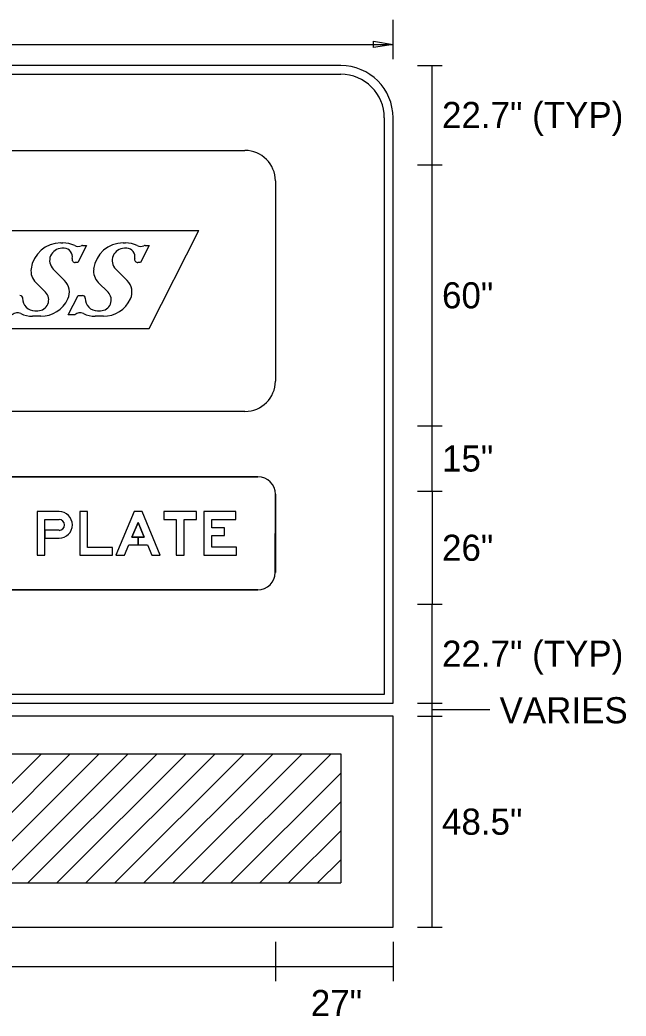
# Model space of a CAD drawing. Extents: x 10268312 to 10268706, y 2142548 to 2142786.
# Drawn here: x 10268686.56 to 10268703.79, y 2142607.94 to 2142636.28 of the extents above; entities that cross this region are included whole.
import ezdxf

# ---------------------------------------------------------------- set-up
doc = ezdxf.new("R2010")
doc.units = 0
for name, color, linetype in [('GSBWFill', 7, 'Continuous'), ('GSDims', 7, 'Continuous'), ('SignPanel', 7, 'Continuous'), ('TextMisc', 7, 'Continuous')]:
    doc.layers.add(name, color=color, linetype=linetype)

msp = doc.modelspace()

# ---------------------------------------------------------------- linework, layer by layer
at = {"layer": 'GSBWFill'}
for p, q in [((10268697.169, 2142635.162), (10268697.169, 2142636.276)), ((10268695.683, 2142634.977), (10268671.916, 2142634.977)), ((10268671.916, 2142634.73), (10268695.683, 2142634.73)), ((10268696.921, 2142633.492), (10268696.921, 2142617.09)), ((10268674.27, 2142623.279), (10268693.329, 2142623.279)), ((10268674.27, 2142623.279), (10268693.329, 2142623.279)), ((10268693.824, 2142622.784), (10268693.824, 2142620.556)), ((10268693.824, 2142622.784), (10268693.824, 2142620.556)), ((10268693.329, 2142620.061), (10268674.27, 2142620.061)), ((10268693.329, 2142620.061), (10268674.27, 2142620.061))]:
    msp.add_line(p, q, dxfattribs=at)
msp.add_lwpolyline([(10268696.921, 2142617.09), (10268670.686, 2142617.09), (10268670.686, 2142616.842), (10268697.169, 2142616.842), (10268697.169, 2142616.842), (10268697.169, 2142633.492)], dxfattribs=at)
for centre, radius, start, end in [((10268695.683, 2142633.492), 1.485, 0, 90), ((10268695.683, 2142633.492), 1.238, 0, 90), ((10268693.329, 2142622.784), 0.495, 0, 90), ((10268693.329, 2142622.784), 0.495, 0, 90), ((10268693.324, 2142620.556), 0.495, 270, 0), ((10268693.324, 2142620.556), 0.495, 270, 0)]:
    msp.add_arc(centre, radius, start, end, dxfattribs=at)
at = {"layer": 'GSDims'}
for p, q in [((10268670.431, 2142635.58), (10268697.169, 2142635.58)), ((10268697.865, 2142634.977), (10268698.561, 2142634.977)), ((10268698.283, 2142632.167), (10268698.283, 2142634.977)), ((10268698.561, 2142634.977), (10268698.561, 2142634.977)), ((10268697.865, 2142632.155), (10268698.561, 2142632.155)), ((10268698.283, 2142624.729), (10268698.283, 2142632.167)), ((10268697.865, 2142624.729), (10268698.561, 2142624.729)), ((10268698.283, 2142622.871), (10268698.283, 2142624.729)), ((10268697.865, 2142622.871), (10268698.561, 2142622.871)), ((10268698.283, 2142622.871), (10268698.283, 2142619.652)), ((10268697.865, 2142619.652), (10268698.561, 2142619.652)), ((10268698.283, 2142616.842), (10268698.283, 2142619.652)), ((10268697.865, 2142616.842), (10268698.561, 2142616.842)), ((10268698.283, 2142616.471), (10268698.283, 2142616.842)), ((10268697.865, 2142616.471), (10268698.561, 2142616.471)), ((10268698.283, 2142616.657), (10268699.925, 2142616.657)), ((10268698.283, 2142610.467), (10268698.283, 2142616.471)), ((10268697.865, 2142610.467), (10268698.561, 2142610.467)), ((10268693.826, 2142610.05), (10268693.826, 2142608.936)), ((10268697.169, 2142610.05), (10268697.169, 2142608.936)), ((10268673.773, 2142609.353), (10268693.826, 2142609.353)), ((10268693.826, 2142609.353), (10268697.169, 2142609.353))]:
    msp.add_line(p, q, dxfattribs=at)
msp.add_lwpolyline([(10268697.169, 2142635.58), (10268696.611, 2142635.487), (10268696.611, 2142635.672)], close=True, dxfattribs=at)
at = {"layer": 'SignPanel'}
for p, q in [((10268674.642, 2142632.563), (10268692.958, 2142632.563)), ((10268693.824, 2142631.697), (10268693.824, 2142626.004)), ((10268682.827, 2142630.283), (10268691.652, 2142630.283)), ((10268690.233, 2142627.499), (10268691.652, 2142630.283)), ((10268687.722, 2142629.935), (10268687.781, 2142629.935)), ((10268687.82, 2142629.78), (10268687.754, 2142629.78)), ((10268688.458, 2142629.858), (10268688.212, 2142629.375)), ((10268688.342, 2142629.858), (10268688.458, 2142629.858)), ((10268689.501, 2142629.935), (10268689.56, 2142629.935)), ((10268689.599, 2142629.78), (10268689.533, 2142629.78)), ((10268690.237, 2142629.858), (10268689.991, 2142629.375)), ((10268690.121, 2142629.858), (10268690.237, 2142629.858)), ((10268688.212, 2142629.375), (10268688.135, 2142629.375)), ((10268689.991, 2142629.375), (10268689.914, 2142629.375)), ((10268687.508, 2142629.187), (10268687.832, 2142628.862)), ((10268689.287, 2142629.187), (10268689.611, 2142628.862)), ((10268687.289, 2142628.53), (10268687.011, 2142628.808)), ((10268689.068, 2142628.53), (10268688.79, 2142628.808)), ((10268687.936, 2142627.886), (10268688.216, 2142628.437)), ((10268688.216, 2142628.437), (10268688.341, 2142628.437)), ((10268687.154, 2142627.847), (10268686.921, 2142627.847)), ((10268686.987, 2142628.002), (10268687.071, 2142628.002)), ((10268688.124, 2142627.886), (10268687.936, 2142627.886)), ((10268688.933, 2142627.847), (10268688.7, 2142627.847)), ((10268688.766, 2142628.002), (10268688.849, 2142628.002)), ((10268682.622, 2142627.499), (10268690.233, 2142627.499)), ((10268692.958, 2142625.138), (10268674.642, 2142625.138)), ((10268693.329, 2142623.279), (10268674.27, 2142623.279)), ((10268693.819, 2142620.556), (10268693.824, 2142622.784)), ((10268687.272, 2142622.066), (10268687.674, 2142622.066)), ((10268687.272, 2142622.066), (10268687.674, 2142622.066)), ((10268687.272, 2142622.066), (10268687.674, 2142622.066)), ((10268687.272, 2142621.534), (10268687.674, 2142621.534)), ((10268674.27, 2142620.061), (10268693.324, 2142620.061)), ((10268697.169, 2142616.471), (10268670.431, 2142616.471)), ((10268697.169, 2142610.467), (10268697.169, 2142616.471)), ((10268670.431, 2142610.467), (10268697.169, 2142610.467))]:
    msp.add_line(p, q, dxfattribs=at)
for points in [[(10268687.674, 2142622.289), (10268687.049, 2142622.289), (10268687.049, 2142621.051), (10268687.272, 2142621.051), (10268687.272, 2142621.534)], [(10268687.674, 2142622.289), (10268687.049, 2142622.289), (10268687.049, 2142621.051), (10268687.272, 2142621.051), (10268687.272, 2142622.066)], [(10268687.674, 2142622.289), (10268687.049, 2142622.289), (10268687.049, 2142621.051), (10268687.272, 2142621.051), (10268687.272, 2142622.066)], [(10268687.674, 2142621.757), (10268687.272, 2142621.757), (10268687.272, 2142622.066)], [(10268687.674, 2142621.757), (10268687.272, 2142621.757), (10268687.272, 2142621.534), (10268687.674, 2142621.534)], [(10268687.674, 2142621.757), (10268687.272, 2142621.757), (10268687.272, 2142621.534), (10268687.674, 2142621.534)]]:
    msp.add_lwpolyline(points, dxfattribs=at)
for points in [[(10268689.19, 2142621.051), (10268689.19, 2142621.268), (10268688.485, 2142621.268), (10268688.485, 2142622.289), (10268688.262, 2142622.289), (10268688.262, 2142621.051)], [(10268689.19, 2142621.051), (10268689.19, 2142621.268), (10268688.485, 2142621.268), (10268688.485, 2142622.289), (10268688.262, 2142622.289), (10268688.262, 2142621.051)], [(10268689.19, 2142621.051), (10268689.19, 2142621.268), (10268688.485, 2142621.268), (10268688.485, 2142622.289), (10268688.262, 2142622.289), (10268688.262, 2142621.051)], [(10268689.653, 2142621.342), (10268690.188, 2142621.342), (10268690.31, 2142621.051), (10268690.552, 2142621.051), (10268690.032, 2142622.289), (10268689.809, 2142622.289), (10268689.29, 2142621.051), (10268689.531, 2142621.051)], [(10268690.095, 2142621.565), (10268689.921, 2142621.565), (10268689.921, 2142621.342), (10268690.188, 2142621.342), (10268690.31, 2142621.051), (10268690.552, 2142621.051), (10268690.032, 2142622.289), (10268689.809, 2142622.289), (10268689.29, 2142621.051), (10268689.531, 2142621.051), (10268689.653, 2142621.342), (10268689.921, 2142621.342), (10268689.921, 2142621.565), (10268689.747, 2142621.565), (10268689.921, 2142621.979)], [(10268690.095, 2142621.565), (10268689.921, 2142621.565), (10268689.921, 2142621.342), (10268690.188, 2142621.342), (10268690.31, 2142621.051), (10268690.552, 2142621.051), (10268690.032, 2142622.289), (10268689.809, 2142622.289), (10268689.29, 2142621.051), (10268689.531, 2142621.051), (10268689.653, 2142621.342), (10268689.921, 2142621.342), (10268689.921, 2142621.565), (10268689.747, 2142621.565), (10268689.921, 2142621.979)], [(10268690.651, 2142622.066), (10268691.004, 2142622.066), (10268691.004, 2142621.051), (10268691.227, 2142621.051), (10268691.227, 2142622.066), (10268691.58, 2142622.066), (10268691.58, 2142622.289), (10268690.651, 2142622.289)], [(10268690.651, 2142622.066), (10268691.004, 2142622.066), (10268691.004, 2142621.051), (10268691.227, 2142621.051), (10268691.227, 2142622.066), (10268691.58, 2142622.066), (10268691.58, 2142622.289), (10268690.651, 2142622.289)], [(10268690.651, 2142622.066), (10268691.004, 2142622.066), (10268691.004, 2142621.051), (10268691.227, 2142621.051), (10268691.227, 2142622.066), (10268691.58, 2142622.066), (10268691.58, 2142622.289), (10268690.651, 2142622.289)], [(10268692.718, 2142621.274), (10268692.013, 2142621.274), (10268692.013, 2142621.607), (10268692.378, 2142621.607), (10268692.378, 2142621.83), (10268692.013, 2142621.83), (10268692.013, 2142622.066), (10268692.7, 2142622.066), (10268692.7, 2142622.289), (10268691.79, 2142622.289), (10268691.79, 2142621.051), (10268692.718, 2142621.051)], [(10268692.718, 2142621.274), (10268692.013, 2142621.274), (10268692.013, 2142621.607), (10268692.378, 2142621.607), (10268692.378, 2142621.83), (10268692.013, 2142621.83), (10268692.013, 2142622.066), (10268692.7, 2142622.066), (10268692.7, 2142622.289), (10268691.79, 2142622.289), (10268691.79, 2142621.051), (10268692.718, 2142621.051)], [(10268692.718, 2142621.274), (10268692.013, 2142621.274), (10268692.013, 2142621.607), (10268692.378, 2142621.607), (10268692.378, 2142621.83), (10268692.013, 2142621.83), (10268692.013, 2142622.066), (10268692.7, 2142622.066), (10268692.7, 2142622.289), (10268691.79, 2142622.289), (10268691.79, 2142621.051), (10268692.718, 2142621.051)], [(10268690.095, 2142621.565), (10268689.921, 2142621.979), (10268689.747, 2142621.565)]]:
    msp.add_lwpolyline(points, close=True, dxfattribs=at)
for centre, radius, start, end in [((10268692.958, 2142631.697), 0.866, 0, 90), ((10268687.722, 2142629.084), 0.851, 90, 172.3089), ((10268687.754, 2142629.432), 0.348, 90, 225), ((10268687.781, 2142629.162), 0.773, 64.0896, 90), ((10268687.82, 2142629.548), 0.232, 345.6915, 90), ((10268688.22, 2142630.066), 0.232, 244.0896, 292.0347), ((10268688.342, 2142629.765), 0.0928, 90, 112.0347), ((10268689.501, 2142629.084), 0.851, 90, 172.3089), ((10268689.533, 2142629.432), 0.348, 90, 225), ((10268689.56, 2142629.162), 0.773, 64.0896, 90), ((10268689.599, 2142629.548), 0.232, 345.6915, 90), ((10268689.999, 2142630.066), 0.232, 244.0896, 292.0347), ((10268690.121, 2142629.765), 0.0928, 90, 112.0347), ((10268688.135, 2142629.468), 0.0928, 165.6915, 270), ((10268689.914, 2142629.468), 0.0928, 165.6915, 270), ((10268687.339, 2142629.136), 0.464, 172.3089, 225), ((10268689.118, 2142629.136), 0.464, 172.3089, 225), ((10268687.504, 2142628.534), 0.464, 334.95, 45), ((10268689.283, 2142628.534), 0.464, 334.95, 45), ((10268686.562, 2142628.359), 0.0773, 358.6664, 90), ((10268687.07, 2142628.311), 0.309, 270, 45), ((10268688.341, 2142628.359), 0.0773, 358.6664, 90), ((10268688.849, 2142628.311), 0.309, 270, 45), ((10268686.987, 2142628.35), 0.348, 178.6665, 270), ((10268687.153, 2142628.698), 0.851, 270, 334.95), ((10268688.766, 2142628.35), 0.348, 178.6665, 270), ((10268688.932, 2142628.698), 0.851, 270, 334.95), ((10268686.493, 2142627.728), 0.217, 64.3795, 133.1892), ((10268686.921, 2142628.62), 0.773, 244.3795, 270), ((10268688.272, 2142627.728), 0.217, 64.3795, 133.1892), ((10268688.7, 2142628.62), 0.773, 244.3795, 270), ((10268692.958, 2142626.004), 0.866, 270, 360), ((10268693.329, 2142622.784), 0.495, 0, 90), ((10268687.674, 2142621.911), 0.378, 270, 90), ((10268687.674, 2142621.911), 0.378, 270, 90), ((10268687.674, 2142621.911), 0.378, 270, 90), ((10268687.674, 2142621.911), 0.155, 270, 90), ((10268687.674, 2142621.911), 0.155, 270, 90), ((10268687.674, 2142621.911), 0.155, 270, 90), ((10268693.324, 2142620.556), 0.495, 270, 0)]:
    msp.add_arc(centre, radius, start, end, dxfattribs=at)
at = {"layer": 'TextMisc'}
for p, q in [((10268671.916, 2142615.395), (10268695.683, 2142615.395)), ((10268683.496, 2142611.729), (10268687.17, 2142615.395)), ((10268684.319, 2142611.729), (10268687.993, 2142615.395)), ((10268685.143, 2142611.729), (10268688.817, 2142615.395)), ((10268685.966, 2142611.729), (10268689.64, 2142615.395)), ((10268686.79, 2142611.729), (10268690.464, 2142615.395)), ((10268687.613, 2142611.729), (10268691.287, 2142615.395)), ((10268688.437, 2142611.729), (10268692.111, 2142615.395)), ((10268689.26, 2142611.729), (10268692.934, 2142615.395)), ((10268690.084, 2142611.729), (10268693.758, 2142615.395)), ((10268690.907, 2142611.729), (10268694.581, 2142615.395)), ((10268691.73, 2142611.729), (10268695.405, 2142615.395)), ((10268695.683, 2142615.395), (10268695.683, 2142611.729)), ((10268692.554, 2142611.729), (10268695.683, 2142614.851)), ((10268693.377, 2142611.729), (10268695.683, 2142614.029)), ((10268694.201, 2142611.729), (10268695.683, 2142613.208)), ((10268695.024, 2142611.729), (10268695.683, 2142612.386)), ((10268671.916, 2142611.729), (10268695.683, 2142611.729))]:
    msp.add_line(p, q, dxfattribs=at)

# ---------------------------------------------------------------- texts
at = {"layer": 'GSDims'}
for s, height, p in [('22.7" (TYP)', 0.74272, (10268698.561, 2142633.201)), ('60"', 0.7427, (10268698.561, 2142628.071)), ('15"', 0.7427, (10268698.561, 2142623.429)), ('26"', 0.7427, (10268698.561, 2142620.89)), ('22.7" (TYP)', 0.74272, (10268698.561, 2142617.876)), ('VARIES', 0.7427, (10268700.196, 2142616.268)), ('48.5"', 0.7427, (10268698.561, 2142613.098)), ('27"', 0.7427, (10268694.831, 2142607.939))]:
    msp.add_text(s, height=height, dxfattribs=at).set_placement(p)

doc.saveas('drawing.dxf')
